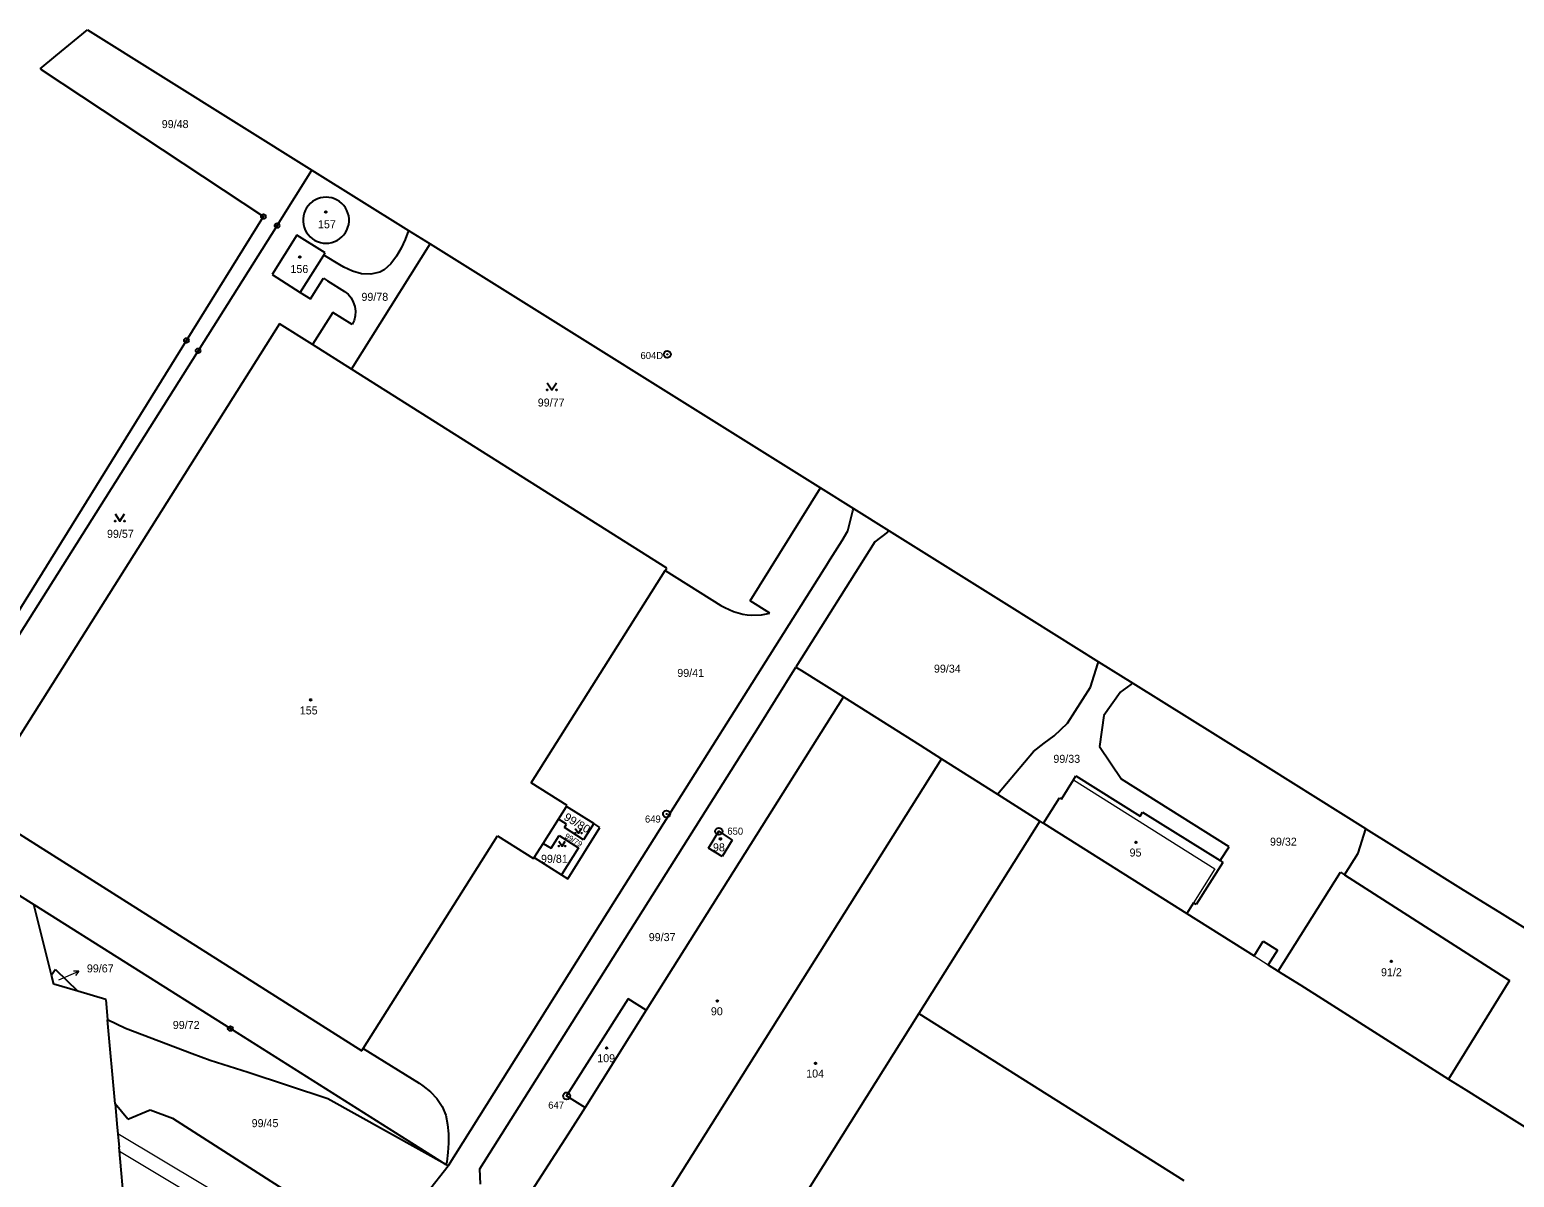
# Model space of a CAD drawing. Extents: x -645290 to -643454, y -1064771 to -1062356.
# Drawn here: x -645131.3 to -644815.8, y -1063365.6 to -1063121.8 of the extents above; entities that cross this region are included whole.
import ezdxf
from ezdxf.enums import TextEntityAlignment as Align

# ---------------------------------------------------------------- set-up
doc = ezdxf.new("R2010")
doc.units = 0
doc.header["$LTSCALE"] = 0.68
for name, color, linetype, lineweight in [('1', 7, 'Continuous', 25), ('13', 7, 'Continuous', 13), ('3', 7, 'Continuous', 25), ('4', 7, 'Continuous', 13), ('5', 7, 'Continuous', 25), ('7', 7, 'Continuous', 13), ('8', 7, 'Continuous', 25)]:
    doc.layers.add(name, color=color, linetype=linetype, lineweight=lineweight)
doc.layers.add('2', color=7, linetype='Continuous')

msp = doc.modelspace()

# ---------------------------------------------------------------- linework, layer by layer
at = {"layer": '1'}
for p, q in [((-645125.74, -1063127.34), (-645119.02, -1063121.76)), ((-645119.02, -1063121.76), (-645071.3, -1063151.59)), ((-645129.04, -1063130.08), (-645125.74, -1063127.34)), ((-645129.04, -1063130.08), (-645128.82, -1063130.23)), ((-645128.82, -1063130.23), (-645081.61, -1063161.47)), ((-645078.73, -1063163.38), (-645071.3, -1063151.59)), ((-645071.3, -1063151.59), (-645050.82, -1063164.39)), ((-645097.97, -1063187.78), (-645081.61, -1063161.47)), ((-645078.73, -1063163.38), (-645095.5, -1063189.97)), ((-645074.5, -1063165.4), (-645079.79, -1063173.8)), ((-645068.51, -1063169.19), (-645074.5, -1063165.4)), ((-645050.82, -1063164.39), (-645051.5, -1063166.35)), ((-645050.82, -1063164.39), (-645046.2, -1063167.28)), ((-645068.79, -1063169.63), (-645068.51, -1063169.19)), ((-645062.93, -1063193.87), (-645046.2, -1063167.28)), ((-645052.38, -1063168.15), (-645053.35, -1063169.87)), ((-645051.5, -1063166.35), (-645052.38, -1063168.15)), ((-645046.2, -1063167.28), (-644963.23, -1063219.12)), ((-645073.81, -1063177.58), (-645068.79, -1063169.63)), ((-645065.4, -1063171.74), (-645068.79, -1063169.63)), ((-645064.51, -1063172.24), (-645065.4, -1063171.74)), ((-645062.69, -1063173.09), (-645064.51, -1063172.24)), ((-645054.52, -1063171.54), (-645055.99, -1063172.8)), ((-645053.35, -1063169.87), (-645054.52, -1063171.54)), ((-645079.79, -1063173.8), (-645073.81, -1063177.58)), ((-645071.62, -1063178.94), (-645068.84, -1063174.55)), ((-645068.84, -1063174.55), (-645068.02, -1063175.09)), ((-645068.02, -1063175.09), (-645064.42, -1063177.41)), ((-645060.78, -1063173.65), (-645062.69, -1063173.09)), ((-645058.8, -1063173.69), (-645060.78, -1063173.65)), ((-645056.86, -1063173.29), (-645058.8, -1063173.69)), ((-645055.99, -1063172.8), (-645056.86, -1063173.29)), ((-645073.81, -1063177.58), (-645071.62, -1063178.94)), ((-645064.42, -1063177.41), (-645063.64, -1063177.98)), ((-645063.64, -1063177.98), (-645062.98, -1063178.75)), ((-645066.84, -1063181.86), (-645071.17, -1063188.67)), ((-645062.77, -1063184.39), (-645066.84, -1063181.86)), ((-645062.98, -1063178.75), (-645062.53, -1063179.66)), ((-645062.53, -1063179.66), (-645062.22, -1063180.6)), ((-645062.22, -1063180.6), (-645062.08, -1063181.58)), ((-645062.08, -1063181.58), (-645062.13, -1063182.57)), ((-645078.17, -1063184.25), (-645142.88, -1063286.77)), ((-645071.17, -1063188.67), (-645078.17, -1063184.25)), ((-645062.36, -1063183.53), (-645062.77, -1063184.39)), ((-645062.13, -1063182.57), (-645062.36, -1063183.53)), ((-645138.37, -1063252.79), (-645097.97, -1063187.78)), ((-645095.5, -1063189.97), (-645135.74, -1063253.8)), ((-645062.93, -1063193.87), (-645071.17, -1063188.67)), ((-644995.93, -1063236.14), (-645062.93, -1063193.87)), ((-644978.17, -1063243.08), (-644963.23, -1063219.12)), ((-644963.23, -1063219.12), (-644956.26, -1063223.48)), ((-644957.42, -1063228.24), (-644956.39, -1063223.96)), ((-644956.39, -1063223.96), (-644956.26, -1063223.48)), ((-644956.26, -1063223.48), (-644948.66, -1063228.23)), ((-644958.66, -1063230.27), (-644957.42, -1063228.24)), ((-644949.04, -1063228.54), (-644951.7, -1063230.59)), ((-644949.04, -1063228.54), (-644948.66, -1063228.23)), ((-644948.66, -1063228.23), (-644923.13, -1063244.19)), ((-644951.7, -1063230.59), (-644968.46, -1063257.21)), ((-644961.62, -1063234.98), (-644958.66, -1063230.27)), ((-644961.62, -1063234.98), (-645007.03, -1063306.92)), ((-645024.73, -1063281.75), (-644996.24, -1063236.63)), ((-644996.24, -1063236.63), (-644995.93, -1063236.14)), ((-644996.24, -1063236.63), (-644984.42, -1063244.1)), ((-644984.42, -1063244.1), (-644983.55, -1063244.56)), ((-644983.55, -1063244.56), (-644981.7, -1063245.37)), ((-644973.98, -1063245.76), (-644978.17, -1063243.08)), ((-644923.13, -1063244.19), (-644904.15, -1063256.05)), ((-644981.7, -1063245.37), (-644979.78, -1063245.92)), ((-644979.78, -1063245.92), (-644978.8, -1063246.09)), ((-644978.8, -1063246.09), (-644977.8, -1063246.13)), ((-644977.8, -1063246.13), (-644975.8, -1063246.06)), ((-644975.8, -1063246.06), (-644973.98, -1063245.76)), ((-644972.83, -1063264.16), (-644968.46, -1063257.21)), ((-644968.46, -1063257.21), (-644967.31, -1063257.94)), ((-644905.87, -1063261.45), (-644904.29, -1063256.47)), ((-644904.29, -1063256.47), (-644904.15, -1063256.05)), ((-644904.15, -1063256.05), (-644896.87, -1063260.6)), ((-644967.31, -1063257.94), (-644958.39, -1063263.52)), ((-644897.22, -1063260.88), (-644896.87, -1063260.6)), ((-644896.87, -1063260.6), (-644873.38, -1063275.28)), ((-644958.39, -1063263.52), (-645000.29, -1063330.1)), ((-644958.39, -1063263.52), (-644942.07, -1063273.81)), ((-644910.76, -1063269.08), (-644905.87, -1063261.45)), ((-644899.58, -1063262.6), (-644903.02, -1063267.47)), ((-644899.58, -1063262.6), (-644897.22, -1063260.88)), ((-644976.39, -1063269.92), (-644972.83, -1063264.16)), ((-645035.63, -1063363.81), (-644976.39, -1063269.92)), ((-644913.56, -1063271.82), (-644910.76, -1063269.08)), ((-644903.02, -1063267.47), (-644903.98, -1063274.08)), ((-644918, -1063275.15), (-644915.73, -1063273.32)), ((-644915.73, -1063273.32), (-644913.56, -1063271.82)), ((-644942.07, -1063273.81), (-644937.5, -1063276.7)), ((-644925.6, -1063284.19), (-644918, -1063275.15)), ((-644903.98, -1063274.08), (-644899.29, -1063281.01)), ((-644847.35, -1063291.55), (-644873.38, -1063275.28)), ((-644937.5, -1063276.7), (-645011.98, -1063394.97)), ((-644937.5, -1063276.7), (-644925.6, -1063284.19)), ((-645017.08, -1063286.61), (-645024.73, -1063281.75)), ((-644912.05, -1063285.27), (-644909.48, -1063281.13)), ((-644909.48, -1063281.13), (-644908.95, -1063280.27)), ((-644908.95, -1063280.27), (-644895.33, -1063288.85)), ((-644876.4, -1063295.38), (-644899.29, -1063281.01)), ((-644925.6, -1063284.19), (-644917.82, -1063289.11)), ((-644915.86, -1063290.34), (-644912.49, -1063285)), ((-644912.49, -1063285), (-644912.05, -1063285.27)), ((-645142.88, -1063286.77), (-645060.68, -1063338.7)), ((-645018.92, -1063289.51), (-645017.21, -1063286.81)), ((-645017.21, -1063286.81), (-645017.08, -1063286.61)), ((-645011.42, -1063290.42), (-645017.21, -1063286.81)), ((-644917.82, -1063289.11), (-644916.6, -1063289.89)), ((-644895.33, -1063288.85), (-644894.81, -1063288.02)), ((-644894.81, -1063288.02), (-644878.32, -1063298.31)), ((-645158.52, -1063289.93), (-645130.42, -1063307.64)), ((-645022.19, -1063294.69), (-645018.92, -1063289.51)), ((-645017.22, -1063290.59), (-645018.92, -1063289.51)), ((-645017.64, -1063291.26), (-645017.22, -1063290.59)), ((-645013.57, -1063293.87), (-645017.64, -1063291.26)), ((-645016.95, -1063302.15), (-645010.1, -1063291.24)), ((-645011.42, -1063290.42), (-645013.57, -1063293.87)), ((-645010.1, -1063291.24), (-645011.42, -1063290.42)), ((-644987.02, -1063295.63), (-644984.84, -1063292.08)), ((-644984.84, -1063292.08), (-644981.99, -1063293.97)), ((-644916.6, -1063289.89), (-644942.34, -1063330.8)), ((-644916.6, -1063289.89), (-644915.86, -1063290.34)), ((-644915.86, -1063290.34), (-644885.41, -1063309.53)), ((-645060.39, -1063338.24), (-645031.85, -1063293.05)), ((-645031.85, -1063293.05), (-645024.21, -1063297.88)), ((-645024.08, -1063297.67), (-645022.19, -1063294.69)), ((-645022.19, -1063294.69), (-645020.48, -1063295.69)), ((-645020.48, -1063295.69), (-645018.74, -1063292.98)), ((-645018.74, -1063292.98), (-645014.66, -1063295.56)), ((-644981.99, -1063293.97), (-644984.15, -1063297.43)), ((-644878.32, -1063298.31), (-644876.4, -1063295.38)), ((-644841.35, -1063295.3), (-644830.61, -1063302.01)), ((-645014.66, -1063295.56), (-645018.28, -1063301.32)), ((-644984.15, -1063297.43), (-644987.02, -1063295.63)), ((-644878.32, -1063298.31), (-644877.73, -1063298.7)), ((-644851.89, -1063301.29), (-644848.98, -1063296.7)), ((-645018.28, -1063301.32), (-645016.95, -1063302.15)), ((-644877.73, -1063298.7), (-644883.38, -1063307.66)), ((-644866, -1063321.77), (-644852.75, -1063300.74)), ((-644852.75, -1063300.74), (-644851.89, -1063301.29)), ((-644851.89, -1063301.29), (-644816.82, -1063323.78)), ((-644830.61, -1063302.01), (-644827.21, -1063304.14)), ((-644827.21, -1063304.14), (-644821.49, -1063307.71)), ((-645129.51, -1063311.28), (-645130.42, -1063307.64)), ((-645130.42, -1063307.64), (-645088.65, -1063333.98)), ((-645007.03, -1063306.92), (-645042.39, -1063363.14)), ((-644883.98, -1063307.27), (-644885.41, -1063309.53)), ((-644883.38, -1063307.66), (-644883.98, -1063307.27)), ((-644821.49, -1063307.71), (-644818.96, -1063309.29)), ((-644885.41, -1063309.53), (-644871.11, -1063318.54)), ((-644818.96, -1063309.29), (-644781.15, -1063332.92)), ((-645126.66, -1063322.65), (-645129.51, -1063311.28)), ((-644871.11, -1063318.54), (-644869.15, -1063315.42)), ((-644869.15, -1063315.42), (-644866.15, -1063317.31)), ((-644866.15, -1063317.31), (-644868.12, -1063320.43)), ((-645125.82, -1063321.41), (-645126.66, -1063322.65)), ((-645126.19, -1063324.53), (-645126.66, -1063322.65)), ((-645125.82, -1063321.41), (-645121.09, -1063326.06)), ((-644865.21, -1063322.27), (-644861.2, -1063324.8)), ((-644816.82, -1063323.78), (-644829.76, -1063344.71)), ((-645121.09, -1063326.06), (-645126.19, -1063324.53)), ((-645115.12, -1063327.84), (-645121.09, -1063326.06)), ((-644861.2, -1063324.8), (-644855.94, -1063328.11)), ((-645115.12, -1063327.84), (-645114.74, -1063332.12)), ((-645004.11, -1063327.7), (-645017.19, -1063348.29)), ((-645000.29, -1063330.1), (-645013.27, -1063350.73)), ((-645000.29, -1063330.1), (-645004.11, -1063327.7)), ((-644855.94, -1063328.11), (-644829.76, -1063344.71)), ((-645113.14, -1063349.95), (-645114.74, -1063332.12)), ((-645110.93, -1063333.96), (-645114.74, -1063332.12)), ((-644942.34, -1063330.8), (-644968.07, -1063371.72)), ((-644942.34, -1063330.8), (-644886, -1063366.24)), ((-645096.75, -1063339.34), (-645110.93, -1063333.96)), ((-645088.65, -1063333.98), (-645042.86, -1063362.85)), ((-645092.96, -1063340.78), (-645096.75, -1063339.34)), ((-645060.68, -1063338.7), (-645060.39, -1063338.24)), ((-645060.39, -1063338.24), (-645048.54, -1063345.62)), ((-645084.87, -1063343.33), (-645092.96, -1063340.78)), ((-645067.9, -1063348.92), (-645084.87, -1063343.33)), ((-645048.54, -1063345.62), (-645047.72, -1063346.18)), ((-644829.76, -1063344.71), (-644826.08, -1063347.04)), ((-645042.39, -1063363.14), (-645067.9, -1063348.92)), ((-645047.72, -1063346.18), (-645046.14, -1063347.44)), ((-645046.14, -1063347.44), (-645044.78, -1063348.87)), ((-645044.78, -1063348.87), (-645043.65, -1063350.53)), ((-645017.19, -1063348.29), (-645013.27, -1063350.73)), ((-644826.08, -1063347.04), (-644797.61, -1063364.94)), ((-645113.14, -1063349.95), (-645112.68, -1063355.04)), ((-645110.43, -1063353.22), (-645113.14, -1063349.95)), ((-645110.43, -1063353.22), (-645105.69, -1063351.29)), ((-645105.69, -1063351.29), (-645100.91, -1063353.03)), ((-645043.65, -1063350.53), (-645042.87, -1063352.36)), ((-645013.27, -1063350.73), (-645016.87, -1063356.45)), ((-645112.68, -1063355.04), (-645112.31, -1063359.17)), ((-645100.91, -1063353.03), (-645071.95, -1063371.61)), ((-645042.87, -1063352.36), (-645042.48, -1063354.34)), ((-645042.48, -1063354.34), (-645042.32, -1063356.32)), ((-645042.29, -1063358.33), (-645042.41, -1063360.32)), ((-645042.32, -1063356.32), (-645042.29, -1063358.33)), ((-645016.87, -1063356.45), (-645027.72, -1063373.25)), ((-645109.58, -1063389.6), (-645112.31, -1063359.17)), ((-645042.41, -1063360.32), (-645042.67, -1063362.3)), ((-645046.85, -1063368.85), (-645042.39, -1063363.14)), ((-645042.67, -1063362.3), (-645042.86, -1063362.85)), ((-645042.39, -1063363.14), (-645042.86, -1063362.85)), ((-645035.46, -1063367.06), (-645035.63, -1063363.81))]:
    msp.add_line(p, q, dxfattribs=at)
msp.add_lwpolyline([(-645068.306, -1063167.13), (-645067.692, -1063167.092), (-645067.089, -1063166.977), (-645066.504, -1063166.787), (-645065.948, -1063166.525), (-645065.429, -1063166.196), (-645064.955, -1063165.804), (-645064.535, -1063165.356), (-645064.173, -1063164.858), (-645063.877, -1063164.32), (-645063.651, -1063163.748), (-645063.498, -1063163.153), (-645063.421, -1063162.543), (-645063.421, -1063161.928), (-645063.498, -1063161.319), (-645063.651, -1063160.723), (-645063.877, -1063160.152), (-645064.173, -1063159.613), (-645064.535, -1063159.116), (-645064.955, -1063158.668), (-645065.429, -1063158.276), (-645065.948, -1063157.947), (-645066.504, -1063157.685), (-645067.089, -1063157.495), (-645067.692, -1063157.38), (-645068.306, -1063157.341), (-645068.919, -1063157.38), (-645069.523, -1063157.495), (-645070.108, -1063157.685), (-645070.664, -1063157.947), (-645071.183, -1063158.276), (-645071.656, -1063158.668), (-645072.077, -1063159.116), (-645072.439, -1063159.613), (-645072.735, -1063160.152), (-645072.961, -1063160.723), (-645073.114, -1063161.319), (-645073.191, -1063161.928), (-645073.191, -1063162.543), (-645073.114, -1063163.153), (-645072.961, -1063163.748), (-645072.735, -1063164.32), (-645072.439, -1063164.858), (-645072.077, -1063165.356), (-645071.656, -1063165.804), (-645071.183, -1063166.196), (-645070.664, -1063166.525), (-645070.108, -1063166.787), (-645069.523, -1063166.977), (-645068.919, -1063167.092)], close=True, dxfattribs=at)
for points in [[(-644848.98, -1063296.7), (-644847.35, -1063291.55), (-644841.35, -1063295.3)], [(-645024.21, -1063297.88), (-645024.08, -1063297.67), (-645018.28, -1063301.32)], [(-644868.12, -1063320.43), (-644866, -1063321.77), (-644865.21, -1063322.27)]]:
    msp.add_lwpolyline(points, dxfattribs=at)
at = {"layer": '13'}
msp.add_lwpolyline([(-644806.97, -1063550.15), (-644805.36, -1063547.59), (-644932.86, -1063467.39), (-645046.68, -1063395.8), (-645043.31, -1063390.69), (-645044.02, -1063386.31), (-645049.24, -1063394.23), (-645112.56, -1063356.35), (-645112.31, -1063359.17), (-645112.23, -1063360.04), (-645049.56, -1063397.54), (-644934.07, -1063470.19)], close=True, dxfattribs=at)
at = {"layer": '3'}
for points in [[(-645021.31, -1063196.789), (-645020.31, -1063198.29), (-645019.31, -1063196.789)], [(-645113.16, -1063224.659), (-645112.16, -1063226.16), (-645111.16, -1063224.659)], [(-645015.34, -1063291.454), (-645014.67, -1063292.46), (-645014, -1063291.454)], [(-645018.84, -1063294.204), (-645018.17, -1063295.21), (-645017.5, -1063294.204)]]:
    msp.add_lwpolyline(points, dxfattribs=at)
for centre, radius in [((-645021.31, -1063198.2895), 0.1), ((-645019.31, -1063198.2895), 0.1), ((-645113.16, -1063226.1595), 0.1), ((-645111.16, -1063226.1595), 0.1), ((-645018.84, -1063295.2096), 0.067), ((-645017.5, -1063295.2096), 0.067), ((-645015.34, -1063292.4596), 0.067), ((-645014, -1063292.4596), 0.067)]:
    msp.add_circle(centre, radius, dxfattribs=at)
at = {"layer": '4'}
for p, q in [((-644909.48, -1063281.13), (-644879.45, -1063300.07)), ((-644879.45, -1063300.07), (-644883.98, -1063307.27)), ((-644871.11, -1063318.54), (-644868.12, -1063320.43))]:
    msp.add_line(p, q, dxfattribs=at)
at = {"layer": '5'}
for centre in [(-645068.3668, -1063160.4792), (-645073.8968, -1063170.0392), (-645071.5768, -1063264.1592), (-644984.5068, -1063293.6892), (-644896.2068, -1063294.4092), (-644841.9468, -1063319.6892), (-644985.1768, -1063328.1392), (-645008.6968, -1063338.1092), (-644964.2968, -1063341.3692)]:
    msp.add_circle(centre, 0.175, dxfattribs=at)
at = {"layer": '7'}
msp.add_line((-645120.848, -1063321.827), (-645121.965, -1063321.758), dxfattribs=at)
msp.add_lwpolyline([(-645125.1, -1063323.64), (-645123.61, -1063323), (-645120.848, -1063321.827), (-645121.574, -1063322.68)], dxfattribs=at)
at = {"layer": '8'}
for centre, radius in [((-645081.61, -1063161.4699), 0.5), ((-645081.61, -1063161.4699), 0.0303), ((-645078.73, -1063163.3799), 0.5), ((-645078.73, -1063163.3799), 0.0303), ((-645097.97, -1063187.7799), 0.5), ((-645097.97, -1063187.7799), 0.0303), ((-645095.5, -1063189.9699), 0.5), ((-645095.5, -1063189.9699), 0.0303), ((-644995.8, -1063190.7398), 0.75), ((-644995.8, -1063190.7398), 0.03), ((-644995.95, -1063288.3898), 0.75), ((-644995.95, -1063288.3898), 0.03), ((-644984.84, -1063292.0798), 0.75), ((-644984.84, -1063292.0798), 0.03), ((-645088.65, -1063333.9799), 0.5), ((-645088.65, -1063333.9799), 0.0303), ((-645017.19, -1063348.2898), 0.75), ((-645017.19, -1063348.2898), 0.03)]:
    msp.add_circle(centre, radius, dxfattribs=at)

# ---------------------------------------------------------------- texts
at = {"layer": '2'}
for s, p in [('99/48', (-645100.38, -1063142.665)), ('99/77', (-645020.48, -1063201.824)), ('99/41', (-644990.83, -1063259.275)), ('99/34', (-644936.29, -1063258.365)), ('99/33', (-644910.91, -1063277.525)), ('98', (-644984.829, -1063296.334)), ('99/32', (-644864.88, -1063295.135)), ('99/81', (-645019.79, -1063298.765)), ('95', (-644896.299, -1063297.435)), ('99/37', (-644996.89, -1063315.405)), ('99/67', (-645116.29, -1063322.054)), ('90', (-644985.269, -1063331.165)), ('99/72', (-645098.03, -1063334.074)), ('109', (-645008.789, -1063341.135)), ('104', (-644964.389, -1063344.395)), ('99/45', (-645081.28, -1063354.935))]:
    msp.add_text(s, height=1.7, dxfattribs=at).set_placement(p, align=Align.CENTER)
for s, p in [('157', (-645070.02, -1063163.945)), ('156', (-645075.88, -1063173.455)), ('99/78', (-645060.79, -1063179.365)), ('99/57', (-645114.86, -1063229.715)), ('155', (-645073.89, -1063267.245)), ('91/2', (-644844.13, -1063322.865))]:
    msp.add_text(s, height=1.7, dxfattribs=at).set_placement(p)
at = {"layer": '2', "width": 1.05}
for s, height, p in [('99/80', 1.7, (-645015.3853, -1063291.0375)), ('99/79', 1.139, (-645015.9873, -1063294.4131))]:
    msp.add_text(s, height=height, rotation=329, dxfattribs=at).set_placement(p, align=Align.CENTER)
at = {"layer": '8'}
for s, p in [('604D', (-645001.49, -1063191.745)), ('649', (-645000.54, -1063290.215)), ('650', (-644983.03, -1063292.794)), ('647', (-645021.1, -1063351.014))]:
    msp.add_text(s, height=1.5, dxfattribs=at).set_placement(p)

doc.saveas('drawing.dxf')
